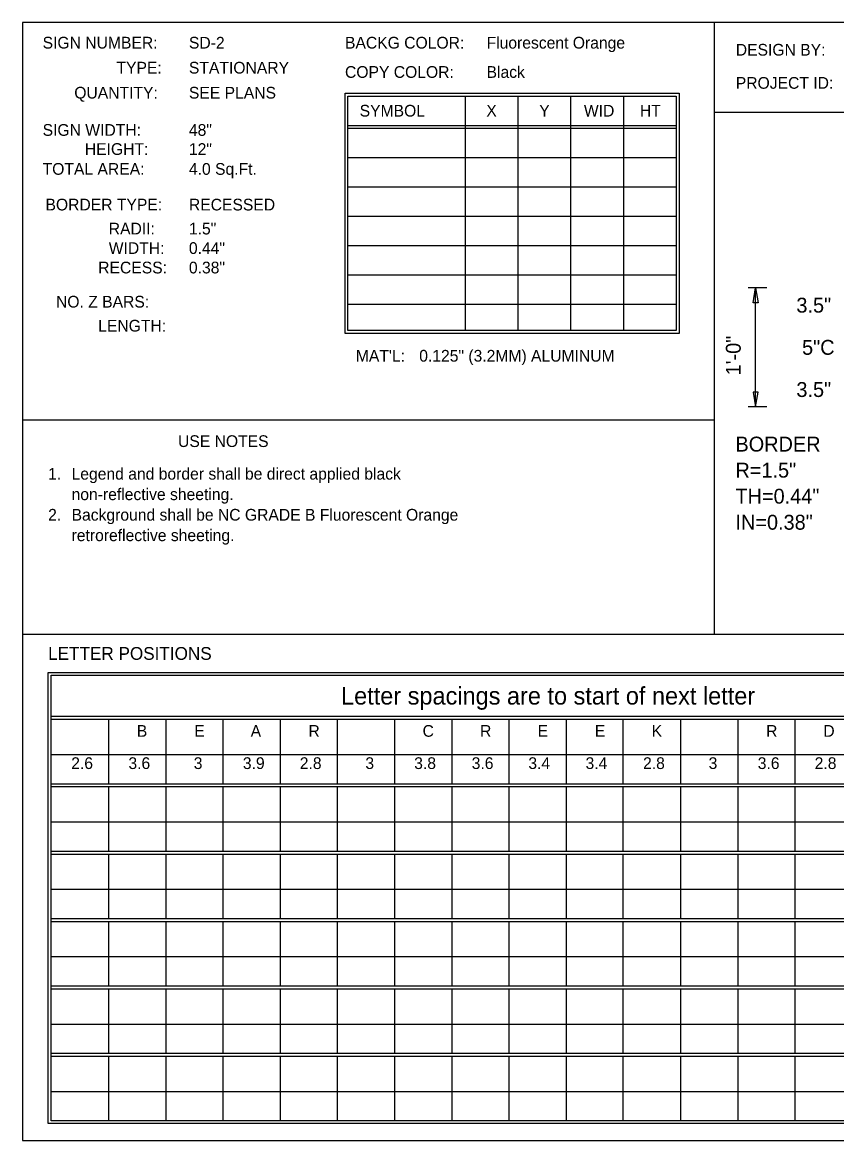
# Model space of a CAD drawing. Extents: x 57.2 to 85.4, y 153.3 to 173.4.
# Drawn here: x 57.21 to 64.05, y 153.34 to 162.73 of the extents above; entities that cross this region are included whole.
import ezdxf

# ---------------------------------------------------------------- set-up
doc = ezdxf.new("R2010")
doc.units = 0
doc.layers.add('Default', color=7, linetype='Continuous')
doc.layers.add('GSDIMS', color=7, linetype='Continuous')

msp = doc.modelspace()

# ---------------------------------------------------------------- linework, layer by layer
at = {"layer": 'Default'}
for p, q in [((69.7172, 162.7348), (57.2061, 162.7348)), ((57.2061, 162.7348), (57.2061, 153.3441)), ((63.0203, 157.5985), (63.0203, 162.7348)), ((59.916, 162.1405), (62.7214, 162.1405)), ((59.916, 160.1225), (59.916, 162.1405)), ((59.9406, 162.1159), (62.6968, 162.1159)), ((59.9406, 160.1471), (59.9406, 162.1159)), ((60.925, 162.1159), (60.925, 160.1471)), ((61.3679, 162.1159), (61.3679, 160.1471)), ((61.8109, 162.1159), (61.8109, 160.1471)), ((62.2538, 162.1159), (62.2538, 160.1471)), ((62.6968, 162.1159), (62.6968, 160.1471)), ((62.7214, 162.1405), (62.7214, 160.1225)), ((63.0203, 161.981), (69.7172, 161.981)), ((59.9406, 161.8698), (62.6968, 161.8698)), ((59.9406, 161.8452), (62.6968, 161.8452)), ((59.9406, 161.5991), (62.6968, 161.5991)), ((59.9406, 161.353), (62.6968, 161.353)), ((59.9406, 161.1069), (62.6968, 161.1069)), ((59.9406, 160.8608), (62.6968, 160.8608)), ((59.9406, 160.6147), (62.6968, 160.6147)), ((59.9406, 160.3686), (62.6968, 160.3686)), ((62.7214, 160.1225), (59.916, 160.1225)), ((62.6968, 160.1471), (59.9406, 160.1471)), ((57.2061, 159.3973), (63.0203, 159.3973)), ((57.2061, 157.5985), (69.7172, 157.5985)), ((57.4226, 157.2766), (69.481, 157.2766)), ((57.4226, 153.4868), (57.4226, 157.2766)), ((57.4473, 157.252), (69.4564, 157.252)), ((57.4473, 153.5114), (57.4473, 157.252)), ((57.4473, 156.9074), (69.4564, 156.9074)), ((57.4473, 156.8828), (69.4564, 156.8828)), ((57.9296, 156.8828), (57.9296, 156.3414)), ((58.4119, 156.8828), (58.4119, 156.3414)), ((58.8893, 156.8828), (58.8893, 156.3414)), ((59.3717, 156.8828), (59.3717, 156.3414)), ((59.8491, 156.8828), (59.8491, 156.3414)), ((60.3314, 156.8828), (60.3314, 156.3414)), ((60.8137, 156.8828), (60.8137, 156.3414)), ((61.2912, 156.8828), (61.2912, 156.3414)), ((61.7735, 156.8828), (61.7735, 156.3414)), ((62.2509, 156.8828), (62.2509, 156.3414)), ((62.7332, 156.8828), (62.7332, 156.3414)), ((63.2156, 156.8828), (63.2156, 156.3414)), ((63.693, 156.8828), (63.693, 156.3414)), ((57.4473, 156.5875), (68.0192, 156.5875)), ((57.4473, 156.3414), (69.4564, 156.3414)), ((57.4473, 156.3168), (69.4564, 156.3168)), ((57.9296, 156.3168), (57.9296, 155.7754)), ((58.4119, 156.3168), (58.4119, 155.7754)), ((58.8893, 156.3168), (58.8893, 155.7754)), ((59.3717, 156.3168), (59.3717, 155.7754)), ((59.8491, 156.3168), (59.8491, 155.7754)), ((60.3314, 156.3168), (60.3314, 155.7754)), ((60.8137, 156.3168), (60.8137, 155.7754)), ((61.2912, 156.3168), (61.2912, 155.7754)), ((61.7735, 156.3168), (61.7735, 155.7754)), ((62.2509, 156.3168), (62.2509, 155.7754)), ((62.7332, 156.3168), (62.7332, 155.7754)), ((63.2156, 156.3168), (63.2156, 155.7754)), ((63.693, 156.3168), (63.693, 155.7754)), ((57.4473, 156.0215), (68.0192, 156.0215)), ((57.4473, 155.7754), (69.4564, 155.7754)), ((57.4473, 155.7508), (69.4564, 155.7508)), ((57.9296, 155.7508), (57.9296, 155.2094)), ((58.4119, 155.7508), (58.4119, 155.2094)), ((58.8893, 155.7508), (58.8893, 155.2094)), ((59.3717, 155.7508), (59.3717, 155.2094)), ((59.8491, 155.7508), (59.8491, 155.2094)), ((60.3314, 155.7508), (60.3314, 155.2094)), ((60.8137, 155.7508), (60.8137, 155.2094)), ((61.2912, 155.7508), (61.2912, 155.2094)), ((61.7735, 155.7508), (61.7735, 155.2094)), ((62.2509, 155.7508), (62.2509, 155.2094)), ((62.7332, 155.7508), (62.7332, 155.2094)), ((63.2156, 155.7508), (63.2156, 155.2094)), ((63.693, 155.7508), (63.693, 155.2094)), ((57.4473, 155.4555), (68.0192, 155.4555)), ((57.4473, 155.2094), (69.4564, 155.2094)), ((57.4473, 155.1848), (69.4564, 155.1848)), ((57.9296, 155.1848), (57.9296, 154.6434)), ((58.4119, 155.1848), (58.4119, 154.6434)), ((58.8893, 155.1848), (58.8893, 154.6434)), ((59.3717, 155.1848), (59.3717, 154.6434)), ((59.8491, 155.1848), (59.8491, 154.6434)), ((60.3314, 155.1848), (60.3314, 154.6434)), ((60.8137, 155.1848), (60.8137, 154.6434)), ((61.2912, 155.1848), (61.2912, 154.6434)), ((61.7735, 155.1848), (61.7735, 154.6434)), ((62.2509, 155.1848), (62.2509, 154.6434)), ((62.7332, 155.1848), (62.7332, 154.6434)), ((63.2156, 155.1848), (63.2156, 154.6434)), ((63.693, 155.1848), (63.693, 154.6434)), ((57.4473, 154.8895), (68.0192, 154.8895)), ((57.4473, 154.6434), (69.4564, 154.6434)), ((57.4473, 154.6188), (69.4564, 154.6188)), ((57.9296, 154.6188), (57.9296, 154.0774)), ((57.9296, 154.6188), (57.9296, 154.0774)), ((58.4119, 154.6188), (58.4119, 154.0774)), ((58.4119, 154.6188), (58.4119, 154.0774)), ((58.8893, 154.6188), (58.8893, 154.0774)), ((58.8893, 154.6188), (58.8893, 154.0774)), ((59.3717, 154.6188), (59.3717, 154.0774)), ((59.3717, 154.6188), (59.3717, 154.0774)), ((59.8491, 154.6188), (59.8491, 154.0774)), ((59.8491, 154.6188), (59.8491, 154.0774)), ((60.3314, 154.6188), (60.3314, 154.0774)), ((60.3314, 154.6188), (60.3314, 154.0774)), ((60.8137, 154.6188), (60.8137, 154.0774)), ((60.8137, 154.6188), (60.8137, 154.0774)), ((61.2912, 154.6188), (61.2912, 154.0774)), ((61.2912, 154.6188), (61.2912, 154.0774)), ((61.7735, 154.6188), (61.7735, 154.0774)), ((61.7735, 154.6188), (61.7735, 154.0774)), ((62.2509, 154.6188), (62.2509, 154.0774)), ((62.2509, 154.6188), (62.2509, 154.0774)), ((62.7332, 154.6188), (62.7332, 154.0774)), ((62.7332, 154.6188), (62.7332, 154.0774)), ((63.2156, 154.6188), (63.2156, 154.0774)), ((63.2156, 154.6188), (63.2156, 154.0774)), ((63.693, 154.6188), (63.693, 154.0774)), ((63.693, 154.6188), (63.693, 154.0774)), ((57.4473, 154.3235), (68.0192, 154.3235)), ((57.4473, 154.0774), (69.4564, 154.0774)), ((57.4473, 154.0528), (69.4564, 154.0528)), ((57.9296, 154.0528), (57.9296, 153.5114)), ((58.4119, 154.0528), (58.4119, 153.5114)), ((58.8893, 154.0528), (58.8893, 153.5114)), ((59.3717, 154.0528), (59.3717, 153.5114)), ((59.8491, 154.0528), (59.8491, 153.5114)), ((60.3314, 154.0528), (60.3314, 153.5114)), ((60.8137, 154.0528), (60.8137, 153.5114)), ((61.2912, 154.0528), (61.2912, 153.5114)), ((61.7735, 154.0528), (61.7735, 153.5114)), ((62.2509, 154.0528), (62.2509, 153.5114)), ((62.7332, 154.0528), (62.7332, 153.5114)), ((63.2156, 154.0528), (63.2156, 153.5114)), ((63.693, 154.0528), (63.693, 153.5114)), ((57.4473, 153.7575), (68.0192, 153.7575)), ((57.4473, 153.7575), (68.0192, 153.7575)), ((69.481, 153.4868), (57.4226, 153.4868)), ((69.4564, 153.5114), (57.4473, 153.5114)), ((57.2061, 153.3441), (69.7172, 153.3441))]:
    msp.add_line(p, q, dxfattribs=at)
at = {"layer": 'GSDIMS'}
for p, q in [((63.4588, 160.5057), (63.3025, 160.5057)), ((63.365, 159.5057), (63.365, 160.5057)), ((63.4588, 159.5057), (63.3025, 159.5057))]:
    msp.add_line(p, q, dxfattribs=at)
for points in [[(63.365, 160.5057), (63.3859, 160.3807), (63.3442, 160.3807)], [(63.365, 159.5057), (63.3859, 159.6307), (63.3442, 159.6307)]]:
    msp.add_lwpolyline(points, close=True, dxfattribs=at)

# ---------------------------------------------------------------- texts
at = {"layer": 'Default'}
for s, height, p in [('SIGN NUMBER:', 0.098425, (57.3763, 162.515)), ('SD-2', 0.09843, (58.605, 162.5148)), ('BACKG COLOR:', 0.098425, (59.916, 162.5148)), ('Fluorescent Orange', 0.098425, (61.105, 162.5148)), ('DESIGN BY:', 0.09843, (63.1982, 162.4555)), ('TYPE:', 0.09843, (57.9964, 162.305)), ('STATIONARY', 0.09843, (58.605, 162.3048)), ('COPY COLOR:', 0.098425, (59.916, 162.2689)), ('Black', 0.09843, (61.105, 162.2689)), ('PROJECT ID:', 0.098425, (63.1982, 162.1772)), ('QUANTITY:', 0.09843, (57.6421, 162.095)), ('SEE PLANS', 0.09843, (58.605, 162.0948)), ('SYMBOL', 0.09843, (60.0391, 161.9436)), ('X', 0.0984, (61.1029, 161.9436)), ('Y', 0.0984, (61.5474, 161.9436)), ('WID', 0.09843, (61.9225, 161.9436)), ('HT', 0.09843, (62.393, 161.9436)), ('SIGN WIDTH:', 0.098425, (57.3763, 161.7821)), ('48"', 0.09843, (58.605, 161.7819)), ('HEIGHT:', 0.09843, (57.7307, 161.6219)), ('12"', 0.09843, (58.605, 161.6217)), ('TOTAL AREA:', 0.098425, (57.3763, 161.4549)), ('4.0 Sq.Ft.', 0.09843, (58.605, 161.4548)), ('BORDER TYPE:', 0.098425, (57.4002, 161.1554)), ('RECESSED', 0.09843, (58.605, 161.1552)), ('RADII:', 0.09843, (57.9317, 160.9537)), ('1.5"', 0.09843, (58.605, 160.9537)), ('WIDTH:', 0.09843, (57.9317, 160.7901)), ('0.44"', 0.09843, (58.605, 160.79)), ('RECESS:', 0.09843, (57.8431, 160.6266)), ('0.38"', 0.09843, (58.605, 160.6266)), ('NO. Z BARS:', 0.098425, (57.4887, 160.3399)), ('LENGTH:', 0.09843, (57.8431, 160.1382)), ("MAT'L:", 0.09843, (60.007, 159.8858)), ('0.125" (3.2MM) ALUMINUM', 0.098425, (60.5394, 159.8858)), ('USE NOTES', 0.09843, (58.5136, 159.1688)), ('1.', 0.09843, (57.4226, 158.895)), ('Legend and border shall be direct applied black', 0.098425, (57.6195, 158.895)), ('non-reflective sheeting.', 0.098425, (57.6195, 158.7228)), ('2.', 0.09843, (57.4226, 158.5506)), ('Background shall be NC GRADE B Fluorescent Orange', 0.098425, (57.6195, 158.5506)), ('retroreflective sheeting.', 0.098425, (57.6195, 158.3784)), ('LETTER POSITIONS', 0.107483, (57.4226, 157.3816)), ('Letter spacings are to start of next letter', 0.147623, (59.8827, 157.0059)), ('B', 0.0984, (58.1674, 156.7355)), ('E', 0.0984, (58.6502, 156.7355)), ('A', 0.0984, (59.1237, 156.7355)), ('R', 0.0984, (59.609, 156.7355)), ('C', 0.0984, (60.5676, 156.7355)), ('R', 0.0984, (61.0505, 156.7355)), ('E', 0.0984, (61.5333, 156.7355)), ('E', 0.0984, (62.0139, 156.7355)), ('K', 0.0984, (62.492, 156.7355)), ('R', 0.0984, (63.453, 156.7355)), ('D', 0.0984, (63.9335, 156.7355)), ('2.6', 0.09843, (57.6165, 156.4648)), ('3.6', 0.09843, (58.097, 156.4648)), ('3', 0.0984, (58.6455, 156.4648)), ('3.9', 0.09843, (59.0581, 156.4648)), ('2.8', 0.09843, (59.5362, 156.4648)), ('3', 0.0984, (60.087, 156.4648)), ('3.8', 0.09843, (60.4972, 156.4648)), ('3.6', 0.09843, (60.9801, 156.4648)), ('3.4', 0.09843, (61.4559, 156.4648)), ('3.4', 0.09843, (61.9364, 156.4648)), ('2.8', 0.09843, (62.4193, 156.4648)), ('3', 0.0984, (62.9701, 156.4648)), ('3.6', 0.09843, (63.3826, 156.4648)), ('2.8', 0.09843, (63.8608, 156.4648))]:
    msp.add_text(s, height=height, dxfattribs=at).set_placement(p)
at = {"layer": 'GSDIMS'}
for s, p in [('3.5"', (63.7073, 160.2974)), ('5"C', (63.7549, 159.9432)), ('3.5"', (63.7073, 159.589)), ('BORDER', (63.1953, 159.1307)), ('R=1.5"', (63.1953, 158.9119)), ('TH=0.44"', (63.1953, 158.6932)), ('IN=0.38"', (63.1953, 158.4744))]:
    msp.add_text(s, height=0.125, dxfattribs=at).set_placement(p)
msp.add_text('1\'-0"', height=0.125, rotation=90, dxfattribs=at).set_placement((63.24, 159.7706))

doc.saveas('drawing.dxf')
